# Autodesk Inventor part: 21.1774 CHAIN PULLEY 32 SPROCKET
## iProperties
Created: 2007-05
Part Number: 21.1774 CHAIN PULLEY 32 SPROCKET
Document SubType Name: Modeling
Designer: Andy Moles
Material: Steel
Density: 7.85 g/cm^3
Mass: 26.0574 g
Surface Area: 22.2442 cm^2
Volume: 3.31941 cm^3
Author: Andy Moles
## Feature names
1. Base1
